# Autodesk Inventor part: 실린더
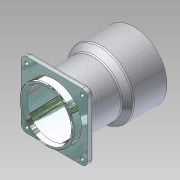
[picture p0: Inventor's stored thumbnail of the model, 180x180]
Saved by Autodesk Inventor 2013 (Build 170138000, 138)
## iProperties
Manager: KYOUNG IL JANG
Company: 한국ATC센터
Created: 2012-10
Part Number: 실린더
Material: 일반
Document SubType Name: 모델링
Density: 1 g/cm^3
Checked By: KYOUNG IL JANG
Vendor: CBT Solutions
Designer: KYOUNG IL JANG
Author: KYOUNG IL JANG
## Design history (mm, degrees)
sketch "스케치1"
  geometry: L1 (0, 0)-(0, 112); L2 (30, 0)-(30, 112); L3 (30, 112)-(42.5, 112); L4 (42.5, 112)-(42.5, 69); L5 (42.5, 69)-(35, 61); L6 (35, 61)-(35, 0); L7 (35, 0)-(30, 0)
  constraints: 14 end point, 4 parallel, 2 point on line, 1 perpendicular, 1 vertical
  dimensions: "d0" = 112 distance of L1.start L1.end; "d2" = 85 diameter of L4 L1; "d3" = 70 diameter of L6 L1; "d5" = 60 diameter of L2 L1; "d33" = 43 distance of L3.end L4.end; "d34" = 51 distance from line of L3 L5.end
revolve "회전1" stored, may be unused: angle "d6" = 90 deg
node "작업 평면1"
sketch "스케치2"
  geometry: L1 (-42.5, 42.5)-(42.5, 42.5); L2 (42.5, 42.5)-(42.5, -42.5); L3 (42.5, -42.5)-(-42.5, -42.5); L4 (-42.5, -42.5)-(-42.5, 42.5); C1 r 35 at (0, 0) reference; 3 further points
  constraints: 8 end point, 2 midpoint, 2 parallel, 2 perpendicular, 1 horizontal, 1 horizontal alignment, 1 vertical alignment
  dimensions: "d8" = 85 distance of L1.end L2.end
extrude "돌출1" join sketch "스케치2" distance "d9" = 8; taper "d10" = 0 deg
fillet "모깎기1" dims "d11" = 7, "d12" = 3
sketch "스케치3"
  geometry: L1 (0, 42.5)-(0, 30); 4 further points
  constraints: 2 end point, 2 vertical alignment, 1 midpoint, 1 point on line, 1 vertical, 2 other
hole "구멍1" sketch "스케치3" at (0, 36.25) diameter "d14" = 4.134; stored, may be unused: countersink angle "d18" = 90 deg, drill point angle "d20" = 118 deg; dims "d15" = 12, "d16" = 4, "d17" = 2, "d19" = 15
sketch "스케치4"
  geometry: C1 r 1.621 at (35.5, -35.5) reference; C2 r 1.621 at (35.5, 35.5) reference; C3 r 1.621 at (-35.5, -35.5) reference; C4 r 1.621 at (-35.5, 35.5) reference; 1 further point
hole "구멍2" sketch "스케치4" at (35.5, 35.5), (35.5, -35.5), (-35.5, -35.5), (-35.5, 35.5) diameter "d26" = 4.5; stored, may be unused: countersink angle "d30" = 90 deg, drill point angle "d32" = 118 deg; dims "d27" = 12, "d28" = 8, "d29" = 4.4, "d31" = 15
chamfer "모따기1" distance "d35" = 5; stored, may be unused: second distance "d36" = 2, angle "d37" = 20 deg
chamfer "모따기2" distance "d38" = 1; stored, may be unused: second distance "d39" = 2, angle "d40" = 20 deg
node "솔리드1"
pattern_circular "원형 패턴1" dims angle "d22" = 360 deg
node "참조1"
node "참조2"
node "참조3"
node "참조4"
other parameters: "KFactor" = 4.4
